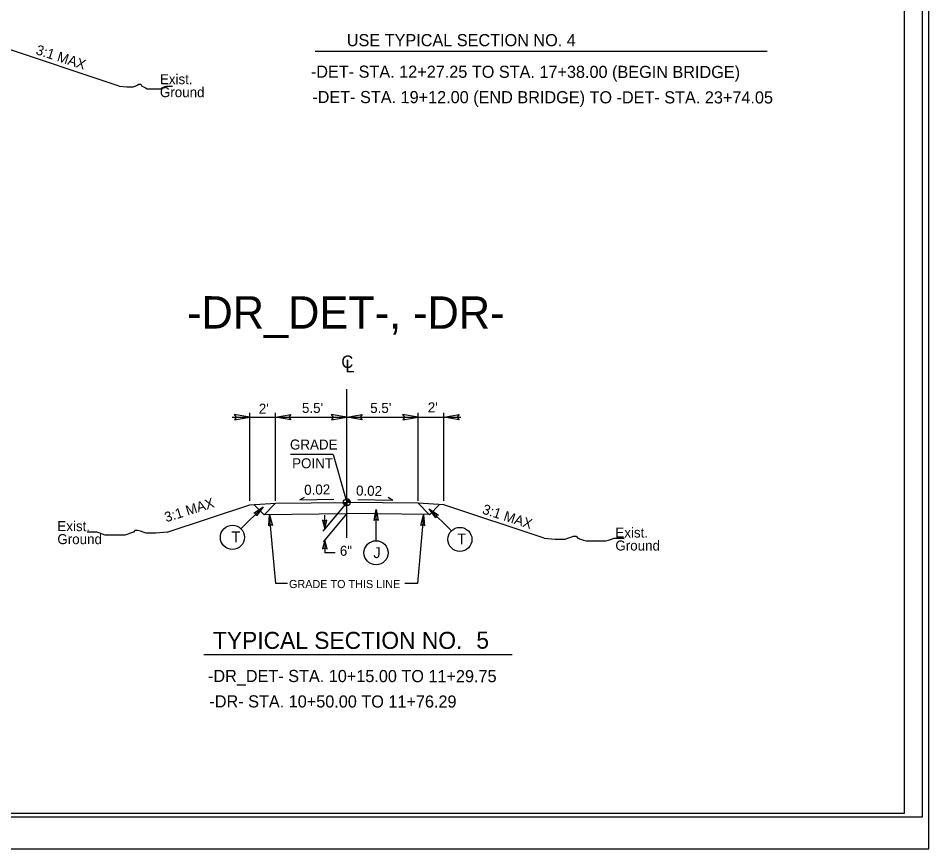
# Model space of a CAD drawing. Extents: x 1497225 to 1499181, y 579958 to 582278.
# Drawn here: x 1498271 to 1498909, y 579958 to 580540 of the extents above; entities that cross this region are included whole.
import ezdxf

# ---------------------------------------------------------------- set-up
doc = ezdxf.new("R2010")
doc.units = 0
for name, color, linetype in [('Old_Level_1', 7, 'Continuous'), ('Old_Level_11', 7, 'Continuous'), ('Old_Level_4', 7, 'Continuous'), ('Prop Dimension Text', 7, 'Continuous'), ('Sheet Cutting Line CELL', 7, 'Continuous'), ('Sheet Plot Border Inside CELL', 7, 'Continuous'), ('Sheet Plot Border Outside CELL', 7, 'Continuous'), ('Sheet Typical CELL', 7, 'Continuous'), ('Typical ID Circle CELL', 7, 'Continuous'), ('Typical Terminator CELL', 7, 'Continuous'), ('Typical Text ID Circle CELL', 7, 'Continuous'), ('Typical Text Label CELL', 7, 'Continuous')]:
    doc.layers.add(name, color=color, linetype=linetype)

# ---------------------------------------------------------------- blocks, each defined once
blk = doc.blocks.new('TERMINATOR')
at = {"layer": 'Typical Terminator CELL'}
blk.add_lwpolyline([(-0.469, 0.081), (0, 0), (-0.471, -0.083), (-0.411, 0)], close=True, dxfattribs=at)

msp = doc.modelspace()

# ---------------------------------------------------------------- linework, layer by layer
at = {"layer": 'Old_Level_1'}
for p, q in [((1498342.06, 580492.63), (1498255.84, 580521.37)), ((1498501.45, 580175.88), (1498501.45, 580280.28)), ((1498421.28, 580260.63), (1498451.45, 580260.63)), ((1498433.48, 580202), (1498433.48, 580263.67)), ((1498451.45, 580202), (1498451.45, 580263.67)), ((1498451.45, 580260.63), (1498501.45, 580260.63)), ((1498501.45, 580260.63), (1498551.45, 580260.63)), ((1498551.45, 580202), (1498551.45, 580263.67)), ((1498551.45, 580260.63), (1498581.5, 580260.63)), ((1498569.42, 580202), (1498569.42, 580263.67)), ((1498492.04, 580234.44), (1498462.06, 580234.44)), ((1498492.04, 580234.44), (1498501.45, 580200.84)), ((1498468.56, 580202.53), (1498471.94, 580204.57)), ((1498468.56, 580202.53), (1498492.38, 580203)), ((1498501.45, 580200.84), (1498501.45, 580203.22)), ((1498533.81, 580202.19), (1498530.43, 580204.23)), ((1498375.59, 580179.88), (1498433.48, 580199.18)), ((1498433.48, 580199.18), (1498451.45, 580200.17)), ((1498436.37, 580199.34), (1498443.49, 580192.21)), ((1498443.49, 580192.21), (1498451.45, 580200.17)), ((1498451.45, 580200.17), (1498501.45, 580200.84)), ((1498501.45, 580200.84), (1498484.69, 580180.67)), ((1498499.07, 580200.84), (1498501.45, 580200.84)), ((1498501.44, 580198.46), (1498501.45, 580200.84)), ((1498501.45, 580200.84), (1498501.44, 580198.46)), ((1498551.45, 580200.17), (1498501.45, 580200.84)), ((1498503.83, 580200.84), (1498501.45, 580200.84)), ((1498533.81, 580202.19), (1498509.29, 580202.68)), ((1498569.42, 580199.18), (1498551.45, 580200.17)), ((1498551.45, 580200.17), (1498559.41, 580192.21)), ((1498559.41, 580192.21), (1498566.53, 580199.34)), ((1498639.67, 580175.76), (1498569.42, 580199.18)), ((1498443.5, 580192.23), (1498501.45, 580193.02)), ((1498451.66, 580143.88), (1498447.44, 580192.17)), ((1498501.56, 580192.99), (1498485.03, 580173.11)), ((1498486.01, 580182.26), (1498486.01, 580191.89)), ((1498559.39, 580192.23), (1498501.45, 580193.02)), ((1498555.34, 580192.17), (1498551.12, 580143.88)), ((1498486.12, 580174.41), (1498486.12, 580165.42)), ((1498493.42, 580165.42), (1498486.12, 580165.42)), ((1498459.98, 580143.88), (1498451.66, 580143.88)), ((1498551.12, 580143.88), (1498542.17, 580143.88))]:
    msp.add_line(p, q, dxfattribs=at)
for points in [[(1498342.06, 580492.63), (1498347.3, 580491.98), (1498348.61, 580491.98), (1498350.58, 580491.98), (1498351.89, 580491.98), (1498353.2, 580492.63), (1498354.51, 580493.29), (1498355.83, 580493.95), (1498357.14, 580493.95), (1498357.8, 580492.63), (1498359.11, 580491.98), (1498360.42, 580491.32), (1498361.73, 580490.67), (1498363.04, 580490.67), (1498364.35, 580490.67), (1498365.66, 580490.67), (1498366.97, 580490.67), (1498368.28, 580490.67), (1498369.6, 580490.67), (1498370.91, 580490.67), (1498372.22, 580491.32), (1498373.53, 580491.98), (1498374.84, 580492.63), (1498376.81, 580492.63), (1498378.12, 580492.63), (1498379.43, 580492.63)], [(1498501.47, 580203.22), (1498501.47, 580203.22), (1498501.47, 580200.84)], [(1498501.52, 580203.22), (1498501.52, 580200.84)], [(1498501.57, 580203.22), (1498501.57, 580200.84)], [(1498501.61, 580203.22), (1498501.61, 580200.84)], [(1498501.66, 580203.21), (1498501.66, 580200.84)], [(1498501.71, 580203.21), (1498501.71, 580200.84)], [(1498501.76, 580203.2), (1498501.76, 580200.84)], [(1498501.8, 580203.2), (1498501.8, 580200.84)], [(1498501.85, 580203.19), (1498501.85, 580200.84)], [(1498501.9, 580203.18), (1498501.9, 580200.84)], [(1498501.95, 580203.17), (1498501.95, 580200.84)], [(1498502, 580203.16), (1498502, 580200.84)], [(1498502.04, 580203.15), (1498502.04, 580200.84)], [(1498502.09, 580203.13), (1498502.09, 580200.84)], [(1498502.14, 580203.12), (1498502.14, 580200.84)], [(1498502.19, 580203.11), (1498502.19, 580200.84)], [(1498502.23, 580203.09), (1498502.23, 580200.84)], [(1498502.28, 580203.08), (1498502.28, 580200.84)], [(1498502.33, 580203.05), (1498502.33, 580200.84)], [(1498502.38, 580203.03), (1498502.38, 580200.84)], [(1498502.42, 580203.01), (1498502.42, 580200.84)], [(1498502.47, 580202.99), (1498502.47, 580200.84)], [(1498502.52, 580202.97), (1498502.52, 580200.84)], [(1498502.57, 580202.94), (1498502.57, 580200.84)], [(1498502.62, 580202.92), (1498502.62, 580200.84)], [(1498502.66, 580202.89), (1498502.66, 580200.84)], [(1498502.71, 580202.86), (1498502.71, 580200.84)], [(1498502.76, 580202.83), (1498502.76, 580200.84)], [(1498502.81, 580202.8), (1498502.81, 580200.84)], [(1498502.85, 580202.76), (1498502.85, 580200.84)], [(1498499.08, 580200.84), (1498499.08, 580200.58)], [(1498499.12, 580200.84), (1498499.12, 580200.3)], [(1498499.17, 580200.84), (1498499.17, 580200.13)], [(1498499.22, 580200.84), (1498499.22, 580199.99)], [(1498499.27, 580200.84), (1498499.27, 580199.88)], [(1498499.32, 580200.84), (1498499.32, 580199.78)], [(1498499.36, 580200.84), (1498499.36, 580199.69)], [(1498499.41, 580200.84), (1498499.41, 580199.6)], [(1498499.46, 580200.84), (1498499.46, 580199.53)], [(1498499.51, 580200.84), (1498499.51, 580199.46)], [(1498499.55, 580200.84), (1498499.55, 580199.4)], [(1498499.6, 580200.84), (1498499.6, 580199.34)], [(1498499.65, 580200.84), (1498499.65, 580199.28)], [(1498499.7, 580200.84), (1498499.7, 580199.23)], [(1498499.74, 580200.84), (1498499.74, 580199.17)], [(1498499.79, 580200.84), (1498499.79, 580199.13)], [(1498499.84, 580200.84), (1498499.84, 580199.08)], [(1498499.89, 580200.84), (1498499.89, 580199.04)], [(1498499.94, 580200.84), (1498499.94, 580199)], [(1498499.98, 580200.84), (1498499.98, 580198.96)], [(1498500.03, 580200.84), (1498500.03, 580198.92)], [(1498500.08, 580200.84), (1498500.08, 580198.89)], [(1498500.13, 580200.84), (1498500.13, 580198.86)], [(1498500.17, 580200.84), (1498500.17, 580198.83)], [(1498500.22, 580200.84), (1498500.22, 580198.8)], [(1498500.27, 580200.84), (1498500.27, 580198.77)], [(1498500.32, 580200.84), (1498500.32, 580198.74)], [(1498500.36, 580200.84), (1498500.36, 580198.72)], [(1498500.41, 580200.84), (1498500.41, 580198.7)], [(1498500.46, 580200.84), (1498500.46, 580198.68)], [(1498500.51, 580200.84), (1498500.51, 580198.65)], [(1498500.55, 580200.84), (1498500.55, 580198.63)], [(1498500.6, 580200.84), (1498500.6, 580198.61)], [(1498500.65, 580200.84), (1498500.65, 580198.6)], [(1498500.7, 580200.84), (1498500.7, 580198.58)], [(1498500.75, 580200.84), (1498500.75, 580198.56)], [(1498500.79, 580200.84), (1498500.79, 580198.55)], [(1498500.84, 580200.84), (1498500.84, 580198.54)], [(1498500.89, 580200.84), (1498500.89, 580198.53)], [(1498500.94, 580200.84), (1498500.94, 580198.52)], [(1498500.98, 580200.84), (1498500.98, 580198.51)], [(1498501.03, 580200.84), (1498501.03, 580198.5)], [(1498501.08, 580200.84), (1498501.08, 580198.49)], [(1498501.13, 580200.84), (1498501.13, 580198.48)], [(1498501.17, 580200.84), (1498501.17, 580198.47)], [(1498501.22, 580200.84), (1498501.22, 580198.47)], [(1498501.27, 580200.84), (1498501.27, 580198.46)], [(1498501.32, 580200.84), (1498501.32, 580198.46)], [(1498501.37, 580200.84), (1498501.37, 580198.46)], [(1498501.41, 580200.84), (1498501.41, 580198.46), (1498501.41, 580198.46)], [(1498502.9, 580202.73), (1498502.9, 580200.84)], [(1498502.95, 580202.69), (1498502.95, 580200.84)], [(1498503, 580202.65), (1498503, 580200.84)], [(1498503.04, 580202.61), (1498503.04, 580200.84)], [(1498503.09, 580202.57), (1498503.09, 580200.84)], [(1498503.14, 580202.52), (1498503.14, 580200.84)], [(1498503.19, 580202.47), (1498503.19, 580200.84)], [(1498503.23, 580202.42), (1498503.23, 580200.84)], [(1498503.28, 580202.36), (1498503.28, 580200.84)], [(1498503.33, 580202.3), (1498503.33, 580200.84)], [(1498503.38, 580202.24), (1498503.38, 580200.84)], [(1498503.43, 580202.17), (1498503.43, 580200.84)], [(1498503.47, 580202.1), (1498503.47, 580200.84)], [(1498503.52, 580202.02), (1498503.52, 580200.84)], [(1498503.57, 580201.93), (1498503.57, 580200.84)], [(1498503.62, 580201.83), (1498503.62, 580200.84)], [(1498503.66, 580201.72), (1498503.66, 580200.84)], [(1498503.71, 580201.59), (1498503.71, 580200.84)], [(1498503.76, 580201.42), (1498503.76, 580200.84)], [(1498503.81, 580201.18), (1498503.81, 580200.84)], [(1498375.59, 580179.88), (1498367.72, 580179.23), (1498365.76, 580179.23), (1498362.8, 580179.23), (1498360.84, 580179.23), (1498358.87, 580179.88), (1498356.9, 580180.54), (1498354.94, 580181.2), (1498352.97, 580181.2), (1498351.98, 580179.88), (1498350.01, 580179.23), (1498348.05, 580178.57), (1498346.08, 580177.91), (1498344.11, 580177.91), (1498342.15, 580177.91), (1498340.18, 580177.91), (1498338.21, 580177.91), (1498336.25, 580177.91), (1498334.28, 580177.91), (1498332.31, 580177.91), (1498330.35, 580178.57), (1498328.38, 580179.23), (1498326.41, 580179.88), (1498323.46, 580179.88), (1498321.49, 580179.88), (1498319.53, 580179.88)], [(1498639.67, 580175.76), (1498647.54, 580175.11), (1498649.51, 580175.11), (1498652.46, 580175.11), (1498654.43, 580175.11), (1498656.39, 580175.76), (1498658.36, 580176.42), (1498660.33, 580177.07), (1498662.29, 580177.07), (1498663.28, 580175.76), (1498665.25, 580175.11), (1498667.21, 580174.45), (1498669.18, 580173.79), (1498671.15, 580173.79), (1498673.11, 580173.79), (1498675.08, 580173.79), (1498677.05, 580173.79), (1498679.01, 580173.79), (1498680.98, 580173.79), (1498682.95, 580173.79), (1498684.92, 580174.45), (1498686.88, 580175.11), (1498688.85, 580175.76), (1498691.8, 580175.76), (1498693.77, 580175.76), (1498695.74, 580175.76)]]:
    msp.add_lwpolyline(points, dxfattribs=at)
msp.add_ellipse((1498501.45, 580200.84), major_axis=(2.38, 0), ratio=0.9995, dxfattribs=at)
for major_axis in [(2.38, 0), (-2.38, 0)]:
    msp.add_ellipse((1498501.45, 580200.84), major_axis=major_axis, ratio=0.9995, start_param=6.283019, end_param=7.853815, dxfattribs=at)
at = {"layer": 'Old_Level_11'}
for points in [[(1498422.76, 580258.74), (1498433.48, 580260.63), (1498422.67, 580262.52), (1498424.05, 580260.63)], [(1498462.18, 580258.74), (1498451.45, 580260.63), (1498462.27, 580262.52), (1498460.89, 580260.63)], [(1498490.72, 580258.74), (1498501.45, 580260.63), (1498490.64, 580262.52), (1498492.01, 580260.63)], [(1498512.18, 580258.74), (1498501.45, 580260.63), (1498512.26, 580262.52), (1498510.89, 580260.63)], [(1498540.72, 580258.74), (1498551.45, 580260.63), (1498540.63, 580262.52), (1498542.01, 580260.63)], [(1498580.14, 580258.74), (1498569.42, 580260.63), (1498580.23, 580262.52), (1498578.85, 580260.63)]]:
    msp.add_lwpolyline(points, close=True, dxfattribs=at)
at = {"layer": 'Old_Level_4'}
for points in [[(1498446.78, 580184.35), (1498447.44, 580192.17), (1498449.48, 580184.54), (1498448.03, 580185.4)], [(1498553.34, 580184.58), (1498555.34, 580192.17), (1498556.03, 580184.3), (1498554.75, 580185.4)]]:
    msp.add_lwpolyline(points, close=True, dxfattribs=at)
at = {"layer": 'Sheet Cutting Line CELL'}
msp.add_line((1497225.23, 579958.02), (1498909.23, 579958.02), dxfattribs=at)
at = {"layer": 'Sheet Plot Border Inside CELL'}
msp.add_lwpolyline([(1498904.73, 581035.57), (1497238.23, 581035.57), (1497238.23, 579980.47), (1498904.73, 579980.47)], close=True, dxfattribs=at)
at = {"layer": 'Sheet Plot Border Outside CELL'}
msp.add_lwpolyline([(1498909.23, 581058.02), (1497225.23, 581058.02), (1497225.23, 579958.02), (1498909.23, 579958.02)], close=True, dxfattribs=at)
at = {"layer": 'Sheet Typical CELL'}
msp.add_lwpolyline([(1498892.23, 581033.02), (1497392.23, 581033.02), (1497392.23, 579983.02), (1498892.23, 579983.02)], close=True, dxfattribs=at)
at = {"layer": 'Typical ID Circle CELL'}
for p, q in [((1498427.35, 580182.31), (1498442.83, 580197.78)), ((1498522, 580173.95), (1498522, 580195.82)), ((1498574.73, 580180.86), (1498559.26, 580196.32))]:
    msp.add_line(p, q, dxfattribs=at)
for centre in [(1498421.38, 580176.33), (1498580.71, 580174.87), (1498522, 580165.49)]:
    msp.add_circle(centre, 8.46, dxfattribs=at)
at = {"layer": 'Typical Terminator CELL'}
for points in [[(1498436.42, 580193.25), (1498442.83, 580197.78), (1498438.3, 580191.31), (1498438.03, 580192.98)], [(1498520.67, 580188.09), (1498522, 580195.82), (1498523.38, 580188.04), (1498522, 580189.03)], [(1498563.79, 580189.91), (1498559.26, 580196.32), (1498565.73, 580191.79), (1498564.06, 580191.52)]]:
    msp.add_lwpolyline(points, close=True, dxfattribs=at)
at = {"layer": 'Typical Text Label CELL'}
for p, q in [((1498479.28, 580517.19), (1498795.89, 580517.19)), ((1498401.33, 580094.13), (1498617.38, 580094.13))]:
    msp.add_line(p, q, dxfattribs=at)

# ---------------------------------------------------------------- block references
at = {"layer": 'Old_Level_4', "xscale": 13.123011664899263, "yscale": -18.835616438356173}
for p, rotation in [((1498486.01, 580182.26), -89.99999999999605), ((1498486.12, 580174.41), 90.00000000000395)]:
    msp.add_blockref('TERMINATOR', p, dxfattribs=dict(at, rotation=rotation))

# ---------------------------------------------------------------- texts
at = {"layer": 'Old_Level_1'}
for s, height, rotation, p in [('3:1 MAX', 7, 342.11243, (1498283.09, 580515.09)), ('-DET- STA. 12+27.25 TO STA. 17+38.00 (BEGIN BRIDGE)', 8.5, 359.94924, (1498476.31, 580498.51)), ('Exist.', 7, 359.94924, (1498370.58, 580493.96)), ('Ground', 7, 359.94924, (1498370.57, 580484.86)), ('-DET- STA. 19+12.00 (END BRIDGE) TO -DET- STA. 23+74.05', 8.5, 359.94924, (1498477.29, 580480.7)), ('-DR_DET-, -DR-', 22.68, 359.94924, (1498389.6, 580322.7)), ('L', 8.73, 359.9469, (1498500.54, 580292.05)), ('0.02', 7, 1.14574, (1498471.69, 580206.1)), ('0.02', 7, 358.85426, (1498507.9, 580205.63)), ('3:1 MAX', 7, 17.44037, (1498375.01, 580186.81)), ('3:1 MAX', 7, 342.11243, (1498595.93, 580193.12)), ('Exist.', 7, 359.94924, (1498298.73, 580180.67)), ('Ground', 7, 359.94924, (1498298.72, 580171.57)), ('Exist.', 7, 359.94924, (1498689.66, 580176.19)), ('Ground', 7, 359.94924, (1498689.66, 580167.09)), ('-DR_DET- STA. 10+15.00 TO 11+29.75', 8.5, 359.94924, (1498404.24, 580074.94)), ('-DR- STA. 10+50.00 TO 11+76.29', 8.5, 359.94924, (1498405.23, 580057.13))]:
    msp.add_text(s, height=height, rotation=rotation, dxfattribs=at).set_placement(p)
for s, height, p in [('C', 8.73, (1498497.63, 580295.03)), ("2'", 7, (1498439.84, 580263.03)), ("5.5'", 7, (1498470.09, 580263.51)), ("5.5'", 7, (1498517.89, 580263.51)), ("2'", 7, (1498558.24, 580263.93)), ('GRADE TO THIS LINE', 5.67, (1498461, 580140.76))]:
    msp.add_text(s, height=height, dxfattribs=at).set_placement(p)
at = {"layer": 'Old_Level_4'}
msp.add_text('6"', height=7, rotation=360, dxfattribs=at).set_placement((1498496.63, 580163.38))
at = {"layer": 'Prop Dimension Text'}
for s, p in [('GRADE', (1498461.69, 580237.88)), ('POINT', (1498463.21, 580224.75))]:
    msp.add_text(s, height=7, rotation=0.00014, dxfattribs=at).set_placement(p)
at = {"layer": 'Typical Text ID Circle CELL'}
for s, p in [('T', (1498420.72, 580172.84)), ('T', (1498578.84, 580171.38)), ('J', (1498520.1, 580161.79))]:
    msp.add_text(s, height=7.58, dxfattribs=at).set_placement(p)
at = {"layer": 'Typical Text Label CELL'}
for s, height, p in [('USE TYPICAL SECTION NO. 4', 8.5, (1498501.49, 580520.57)), ('TYPICAL SECTION NO.  ', 11.9356, (1498407.74, 580098.13)), ('5', 11.94, (1498592.26, 580098.29))]:
    msp.add_text(s, height=height, dxfattribs=at).set_placement(p)

doc.saveas('drawing.dxf')
